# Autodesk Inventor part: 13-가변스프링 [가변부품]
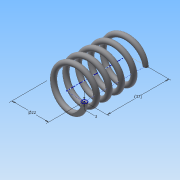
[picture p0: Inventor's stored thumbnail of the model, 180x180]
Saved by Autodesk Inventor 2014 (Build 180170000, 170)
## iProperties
Created: 2015-09
Part Number: 13-가변스프링 [가변부품]
Material: 강철, 탄소
Document SubType Name: Modeling
Designer: study
Density: 7.87 g/cm^3
Appearance: 반연마
Mass: 18.8111 g
Surface Area: 32.4633 cm^2
Volume: 2.39023 cm^3
Author: study
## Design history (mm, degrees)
sketch "스케치1"
  geometry: L1 (0, 0)-(11, 0); L2 (11, 0)-(11, 28.893); L3 (11, 28.893)-(0, 28.893); L4 (0, 28.893)-(0, 0); C1 r 1.5 at (11, 0)
  constraints: 8 end point, 2 parallel, 1 centre point, 1 coincident, 1 horizontal, 1 perpendicular
  dimensions: "d0" = 22 diameter of L2 L4; "d1" = 28.89259 distance of L1.end L2.end (derived); "d2" = 3 diameter of C1
feature "코일1" pitch "d3" = 10; turns "d5" = 5; dims "d4" = 28.89259 (= d1), "d6" = 0, angle "d7" = 90 deg, angle "d8" = 90 deg, "d9" = 0, "d10" = 0
node "작업 평면1"
sketch "스케치2"
  geometry: L1 (-12.5, 0)-(-9.5, 0) reference; 1 further point
  constraints: 1 horizontal alignment
extrude "돌출1" cut sketch "스케치2" stored distance "d12" = 10; taper "d13" = 0 deg
node "작업 평면2"
sketch "스케치3"
  geometry: L1 (-9.5, 0)-(-12.5, 0) reference; 1 further point
  constraints: 1 horizontal alignment
extrude "돌출2" cut sketch "스케치3" stored distance "d15" = 10; taper "d16" = 0 deg
node "솔리드1"
node "절단 모서리 투영1"
node "절단 모서리 투영2"
other parameters: "d11" = 0, "d14" = 28.89259 (= d1)
